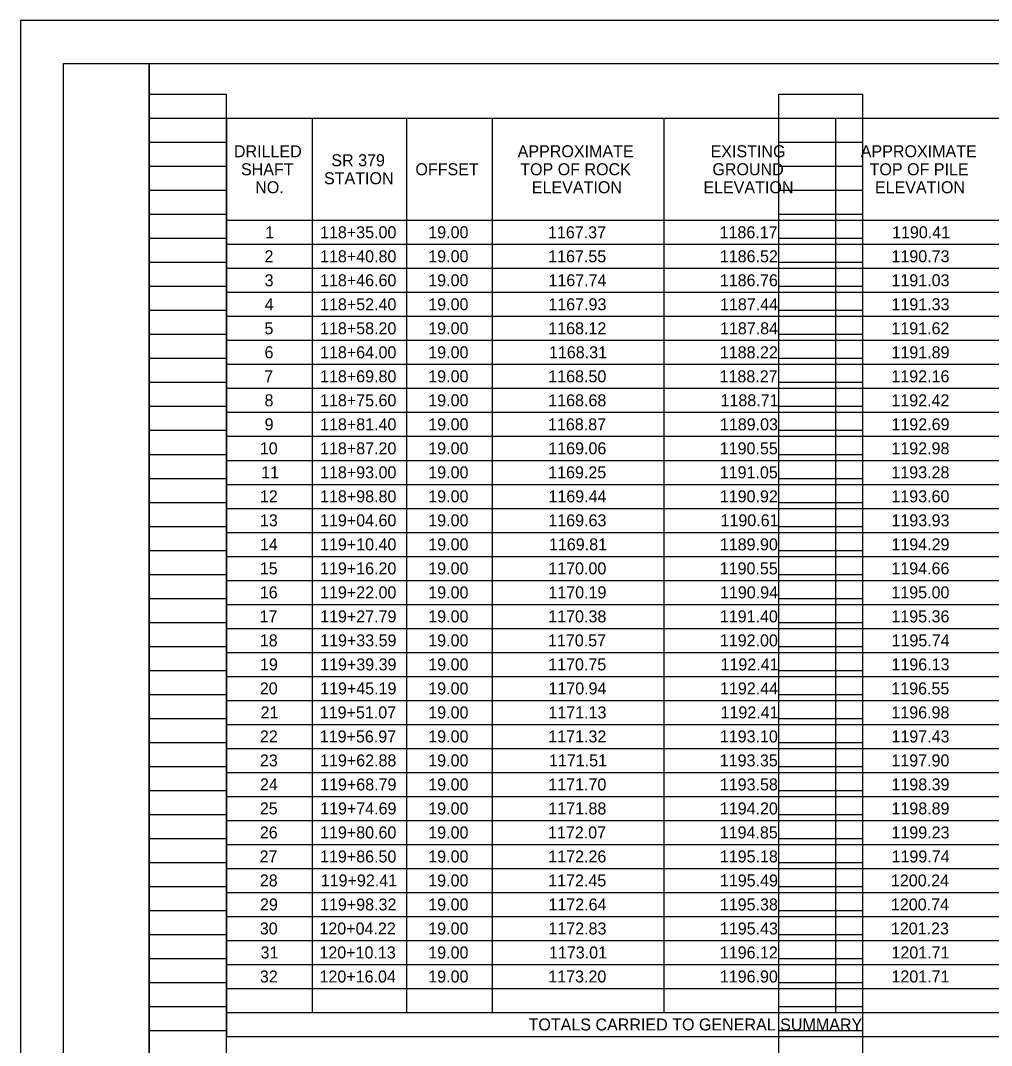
# Model space of a CAD drawing. Extents: x 0 to 34, y 0 to 22.
# Drawn here: x 0 to 11.32, y 10.04 to 22 of the extents above; entities that cross this region are included whole.
import ezdxf

# ---------------------------------------------------------------- set-up
doc = ezdxf.new("R2010")
doc.units = 0
for name, color, linetype in [('RD_P_Text', 7, 'Continuous'), ('SC_Scratch1', 7, 'Continuous'), ('SC_Scratch2', 7, 'Continuous'), ('SH_Border', 7, 'Continuous'), ('SH_Cut_Line', 7, 'Continuous')]:
    doc.layers.add(name, color=color, linetype=linetype)

msp = doc.modelspace()

# ---------------------------------------------------------------- linework, layer by layer
at = {"layer": 'RD_P_Text'}
for p, q in [((2.4, 20.86), (20.1, 20.86)), ((2.4, 20.86), (2.4, 10.15)), ((3.4, 20.86), (3.4, 10.43)), ((4.5, 20.86), (4.5, 10.43)), ((5.5, 20.86), (5.5, 10.43)), ((7.5, 20.86), (7.5, 10.43)), ((9.5, 20.86), (9.5, 10.43)), ((2.4, 19.67), (20.1, 19.67)), ((2.4, 19.39), (20.1, 19.39)), ((2.4, 19.11), (20.1, 19.11)), ((2.4, 18.83), (20.1, 18.83)), ((2.4, 18.55), (20.1, 18.55)), ((2.4, 18.27), (20.1, 18.27)), ((2.4, 17.99), (20.1, 17.99)), ((2.4, 17.71), (20.1, 17.71)), ((2.4, 17.43), (20.1, 17.43)), ((2.4, 17.15), (20.1, 17.15)), ((2.4, 16.87), (20.1, 16.87)), ((2.4, 16.59), (20.1, 16.59)), ((2.4, 16.31), (20.1, 16.31)), ((2.4, 16.03), (20.1, 16.03)), ((2.4, 15.75), (20.1, 15.75)), ((2.4, 15.47), (20.1, 15.47)), ((2.4, 15.19), (20.1, 15.19)), ((2.4, 14.91), (20.1, 14.91)), ((2.4, 14.63), (20.1, 14.63)), ((2.4, 14.35), (20.1, 14.35)), ((2.4, 14.07), (20.1, 14.07)), ((2.4, 13.79), (20.1, 13.79)), ((2.4, 13.51), (20.1, 13.51)), ((2.4, 13.23), (20.1, 13.23)), ((2.4, 12.95), (20.1, 12.95)), ((2.4, 12.67), (20.1, 12.67)), ((2.4, 12.39), (20.1, 12.39)), ((2.4, 12.11), (20.1, 12.11)), ((2.4, 11.83), (20.1, 11.83)), ((2.4, 11.55), (20.1, 11.55)), ((2.4, 11.27), (20.1, 11.27)), ((2.4, 10.99), (20.1, 10.99)), ((2.4, 10.71), (20.1, 10.71)), ((2.4, 10.43), (20.1, 10.43)), ((2.4, 10.15), (20.1, 10.15))]:
    msp.add_line(p, q, dxfattribs=at)
at = {"layer": 'SC_Scratch1'}
for p, q in [((2.9, 19.53), (2.9, 19.53)), ((3.95, 19.53), (3.95, 19.53)), ((5, 19.53), (5, 19.53)), ((6.5, 19.53), (6.5, 19.53)), ((8.5, 19.53), (8.5, 19.53)), ((10.5, 19.53), (10.5, 19.53)), ((2.9, 19.25), (2.9, 19.25)), ((3.95, 19.25), (3.95, 19.25)), ((5, 19.25), (5, 19.25)), ((6.5, 19.25), (6.5, 19.25)), ((8.5, 19.25), (8.5, 19.25)), ((10.5, 19.25), (10.5, 19.25)), ((2.9, 18.97), (2.9, 18.97)), ((3.95, 18.97), (3.95, 18.97)), ((5, 18.97), (5, 18.97)), ((6.5, 18.97), (6.5, 18.97)), ((8.5, 18.97), (8.5, 18.97)), ((10.5, 18.97), (10.5, 18.97)), ((2.9, 18.69), (2.9, 18.69)), ((3.95, 18.69), (3.95, 18.69)), ((5, 18.69), (5, 18.69)), ((6.5, 18.69), (6.5, 18.69)), ((8.5, 18.69), (8.5, 18.69)), ((10.5, 18.69), (10.5, 18.69)), ((2.9, 18.41), (2.9, 18.41)), ((3.95, 18.41), (3.95, 18.41)), ((5, 18.41), (5, 18.41)), ((6.5, 18.41), (6.5, 18.41)), ((8.5, 18.41), (8.5, 18.41)), ((10.5, 18.41), (10.5, 18.41)), ((2.9, 18.13), (2.9, 18.13)), ((3.95, 18.13), (3.95, 18.13)), ((5, 18.13), (5, 18.13)), ((6.5, 18.13), (6.5, 18.13)), ((8.5, 18.13), (8.5, 18.13)), ((10.5, 18.13), (10.5, 18.13)), ((2.9, 17.85), (2.9, 17.85)), ((3.95, 17.85), (3.95, 17.85)), ((5, 17.85), (5, 17.85)), ((6.5, 17.85), (6.5, 17.85)), ((8.5, 17.85), (8.5, 17.85)), ((10.5, 17.85), (10.5, 17.85)), ((2.9, 17.57), (2.9, 17.57)), ((3.95, 17.57), (3.95, 17.57)), ((5, 17.57), (5, 17.57)), ((6.5, 17.57), (6.5, 17.57)), ((8.5, 17.57), (8.5, 17.57)), ((10.5, 17.57), (10.5, 17.57)), ((2.9, 17.29), (2.9, 17.29)), ((3.95, 17.29), (3.95, 17.29)), ((5, 17.29), (5, 17.29)), ((6.5, 17.29), (6.5, 17.29)), ((8.5, 17.29), (8.5, 17.29)), ((10.5, 17.29), (10.5, 17.29)), ((2.9, 17.01), (2.9, 17.01)), ((3.95, 17.01), (3.95, 17.01)), ((5, 17.01), (5, 17.01)), ((6.5, 17.01), (6.5, 17.01)), ((8.5, 17.01), (8.5, 17.01)), ((10.5, 17.01), (10.5, 17.01)), ((2.9, 16.73), (2.9, 16.73)), ((3.95, 16.73), (3.95, 16.73)), ((5, 16.73), (5, 16.73)), ((6.5, 16.73), (6.5, 16.73)), ((8.5, 16.73), (8.5, 16.73)), ((10.5, 16.73), (10.5, 16.73)), ((2.9, 16.45), (2.9, 16.45)), ((3.95, 16.45), (3.95, 16.45)), ((5, 16.45), (5, 16.45)), ((6.5, 16.45), (6.5, 16.45)), ((8.5, 16.45), (8.5, 16.45)), ((10.5, 16.45), (10.5, 16.45)), ((2.9, 16.17), (2.9, 16.17)), ((3.95, 16.17), (3.95, 16.17)), ((5, 16.17), (5, 16.17)), ((6.5, 16.17), (6.5, 16.17)), ((8.5, 16.17), (8.5, 16.17)), ((10.5, 16.17), (10.5, 16.17)), ((2.9, 15.89), (2.9, 15.89)), ((3.95, 15.89), (3.95, 15.89)), ((5, 15.89), (5, 15.89)), ((6.5, 15.89), (6.5, 15.89)), ((8.5, 15.89), (8.5, 15.89)), ((10.5, 15.89), (10.5, 15.89)), ((2.9, 15.61), (2.9, 15.61)), ((3.95, 15.61), (3.95, 15.61)), ((5, 15.61), (5, 15.61)), ((6.5, 15.61), (6.5, 15.61)), ((8.5, 15.61), (8.5, 15.61)), ((10.5, 15.61), (10.5, 15.61)), ((2.9, 15.33), (2.9, 15.33)), ((3.95, 15.33), (3.95, 15.33)), ((5, 15.33), (5, 15.33)), ((6.5, 15.33), (6.5, 15.33)), ((8.5, 15.33), (8.5, 15.33)), ((10.5, 15.33), (10.5, 15.33)), ((2.9, 15.05), (2.9, 15.05)), ((3.95, 15.05), (3.95, 15.05)), ((5, 15.05), (5, 15.05)), ((6.5, 15.05), (6.5, 15.05)), ((8.5, 15.05), (8.5, 15.05)), ((10.5, 15.05), (10.5, 15.05)), ((2.9, 14.77), (2.9, 14.77)), ((3.95, 14.77), (3.95, 14.77)), ((5, 14.77), (5, 14.77)), ((6.5, 14.77), (6.5, 14.77)), ((8.5, 14.77), (8.5, 14.77)), ((10.5, 14.77), (10.5, 14.77)), ((2.9, 14.49), (2.9, 14.49)), ((3.95, 14.49), (3.95, 14.49)), ((5, 14.49), (5, 14.49)), ((6.5, 14.49), (6.5, 14.49)), ((8.5, 14.49), (8.5, 14.49)), ((10.5, 14.49), (10.5, 14.49)), ((2.9, 14.21), (2.9, 14.21)), ((3.95, 14.21), (3.95, 14.21)), ((5, 14.21), (5, 14.21)), ((6.5, 14.21), (6.5, 14.21)), ((8.5, 14.21), (8.5, 14.21)), ((10.5, 14.21), (10.5, 14.21)), ((2.9, 13.93), (2.9, 13.93)), ((3.95, 13.93), (3.95, 13.93)), ((5, 13.93), (5, 13.93)), ((6.5, 13.93), (6.5, 13.93)), ((8.5, 13.93), (8.5, 13.93)), ((10.5, 13.93), (10.5, 13.93)), ((2.9, 13.65), (2.9, 13.65)), ((3.95, 13.65), (3.95, 13.65)), ((5, 13.65), (5, 13.65)), ((6.5, 13.65), (6.5, 13.65)), ((8.5, 13.65), (8.5, 13.65)), ((10.5, 13.65), (10.5, 13.65)), ((2.9, 13.37), (2.9, 13.37)), ((3.95, 13.37), (3.95, 13.37)), ((5, 13.37), (5, 13.37)), ((6.5, 13.37), (6.5, 13.37)), ((8.5, 13.37), (8.5, 13.37)), ((10.5, 13.37), (10.5, 13.37)), ((2.9, 13.09), (2.9, 13.09)), ((3.95, 13.09), (3.95, 13.09)), ((5, 13.09), (5, 13.09)), ((6.5, 13.09), (6.5, 13.09)), ((8.5, 13.09), (8.5, 13.09)), ((10.5, 13.09), (10.5, 13.09)), ((2.9, 12.81), (2.9, 12.81)), ((3.95, 12.81), (3.95, 12.81)), ((5, 12.81), (5, 12.81)), ((6.5, 12.81), (6.5, 12.81)), ((8.5, 12.81), (8.5, 12.81)), ((10.5, 12.81), (10.5, 12.81)), ((2.9, 12.53), (2.9, 12.53)), ((3.95, 12.53), (3.95, 12.53)), ((5, 12.53), (5, 12.53)), ((6.5, 12.53), (6.5, 12.53)), ((8.5, 12.53), (8.5, 12.53)), ((10.5, 12.53), (10.5, 12.53)), ((2.9, 12.25), (2.9, 12.25)), ((3.95, 12.25), (3.95, 12.25)), ((5, 12.25), (5, 12.25)), ((6.5, 12.25), (6.5, 12.25)), ((8.5, 12.25), (8.5, 12.25)), ((10.5, 12.25), (10.5, 12.25)), ((2.9, 11.97), (2.9, 11.97)), ((3.95, 11.97), (3.95, 11.97)), ((5, 11.97), (5, 11.97)), ((6.5, 11.97), (6.5, 11.97)), ((8.5, 11.97), (8.5, 11.97)), ((10.5, 11.97), (10.5, 11.97)), ((2.9, 11.69), (2.9, 11.69)), ((3.95, 11.69), (3.95, 11.69)), ((5, 11.69), (5, 11.69)), ((6.5, 11.69), (6.5, 11.69)), ((8.5, 11.69), (8.5, 11.69)), ((10.5, 11.69), (10.5, 11.69)), ((2.9, 11.41), (2.9, 11.41)), ((3.95, 11.41), (3.95, 11.41)), ((5, 11.41), (5, 11.41)), ((6.5, 11.41), (6.5, 11.41)), ((8.5, 11.41), (8.5, 11.41)), ((10.5, 11.41), (10.5, 11.41)), ((2.9, 11.13), (2.9, 11.13)), ((3.95, 11.13), (3.95, 11.13)), ((5, 11.13), (5, 11.13)), ((6.5, 11.13), (6.5, 11.13)), ((8.5, 11.13), (8.5, 11.13)), ((10.5, 11.13), (10.5, 11.13)), ((2.9, 10.85), (2.9, 10.85)), ((3.95, 10.85), (3.95, 10.85)), ((5, 10.85), (5, 10.85)), ((6.5, 10.85), (6.5, 10.85)), ((8.5, 10.85), (8.5, 10.85)), ((10.5, 10.85), (10.5, 10.85))]:
    msp.add_line(p, q, dxfattribs=at)
at = {"layer": 'SC_Scratch2'}
for p, q in [((1.5, 0.98), (1.5, 21.14)), ((1.5, 21.14), (2.4, 21.14)), ((2.4, 0.98), (2.4, 21.14)), ((8.84, 0.98), (8.84, 21.14)), ((8.84, 21.14), (9.82, 21.14)), ((9.82, 0.98), (9.82, 21.14)), ((1.5, 20.86), (2.4, 20.86)), ((8.84, 20.86), (9.82, 20.86)), ((1.5, 20.58), (2.4, 20.58)), ((8.84, 20.58), (9.82, 20.58)), ((1.5, 20.3), (2.4, 20.3)), ((8.84, 20.3), (9.82, 20.3)), ((1.5, 20.02), (2.4, 20.02)), ((8.84, 20.02), (9.82, 20.02)), ((1.5, 19.74), (2.4, 19.74)), ((8.84, 19.74), (9.82, 19.74)), ((1.5, 19.46), (2.4, 19.46)), ((8.84, 19.46), (9.82, 19.46)), ((1.5, 19.18), (2.4, 19.18)), ((8.84, 19.18), (9.82, 19.18)), ((1.5, 18.9), (2.4, 18.9)), ((8.84, 18.9), (9.82, 18.9)), ((1.5, 18.62), (2.4, 18.62)), ((8.84, 18.62), (9.82, 18.62)), ((1.5, 18.34), (2.4, 18.34)), ((8.84, 18.34), (9.82, 18.34)), ((1.5, 18.06), (2.4, 18.06)), ((8.84, 18.06), (9.82, 18.06)), ((1.5, 17.78), (2.4, 17.78)), ((8.84, 17.78), (9.82, 17.78)), ((1.5, 17.5), (2.4, 17.5)), ((8.84, 17.5), (9.82, 17.5)), ((1.5, 17.22), (2.4, 17.22)), ((8.84, 17.22), (9.82, 17.22)), ((1.5, 16.94), (2.4, 16.94)), ((8.84, 16.94), (9.82, 16.94)), ((1.5, 16.66), (2.4, 16.66)), ((8.84, 16.66), (9.82, 16.66)), ((1.5, 16.38), (2.4, 16.38)), ((8.84, 16.38), (9.82, 16.38)), ((1.5, 16.1), (2.4, 16.1)), ((8.84, 16.1), (9.82, 16.1)), ((1.5, 15.82), (2.4, 15.82)), ((8.84, 15.82), (9.82, 15.82)), ((1.5, 15.54), (2.4, 15.54)), ((8.84, 15.54), (9.82, 15.54)), ((1.5, 15.26), (2.4, 15.26)), ((8.84, 15.26), (9.82, 15.26)), ((1.5, 14.98), (2.4, 14.98)), ((8.84, 14.98), (9.82, 14.98)), ((1.5, 14.7), (2.4, 14.7)), ((8.84, 14.7), (9.82, 14.7)), ((1.5, 14.42), (2.4, 14.42)), ((8.84, 14.42), (9.82, 14.42)), ((1.5, 14.14), (2.4, 14.14)), ((8.84, 14.14), (9.82, 14.14)), ((1.5, 13.86), (2.4, 13.86)), ((8.84, 13.86), (9.82, 13.86)), ((1.5, 13.58), (2.4, 13.58)), ((8.84, 13.58), (9.82, 13.58)), ((1.5, 13.3), (2.4, 13.3)), ((8.84, 13.3), (9.82, 13.3)), ((1.5, 13.02), (2.4, 13.02)), ((8.84, 13.02), (9.82, 13.02)), ((1.5, 12.74), (2.4, 12.74)), ((8.84, 12.74), (9.82, 12.74)), ((1.5, 12.46), (2.4, 12.46)), ((8.84, 12.46), (9.82, 12.46)), ((1.5, 12.18), (2.4, 12.18)), ((8.84, 12.18), (9.82, 12.18)), ((1.5, 11.9), (2.4, 11.9)), ((8.84, 11.9), (9.82, 11.9)), ((1.5, 11.62), (2.4, 11.62)), ((8.84, 11.62), (9.82, 11.62)), ((1.5, 11.34), (2.4, 11.34)), ((8.84, 11.34), (9.82, 11.34)), ((1.5, 11.06), (2.4, 11.06)), ((8.84, 11.06), (9.82, 11.06)), ((1.5, 10.78), (2.4, 10.78)), ((8.84, 10.78), (9.82, 10.78)), ((1.5, 10.5), (2.4, 10.5)), ((8.84, 10.5), (9.82, 10.5)), ((1.5, 10.22), (2.4, 10.22)), ((8.84, 10.22), (9.82, 10.22))]:
    msp.add_line(p, q, dxfattribs=at)
at = {"layer": 'SH_Border'}
for points in [[(0.5, 21.5), (1.5, 21.5), (1.5, 0.5), (0.5, 0.5)], [(1.5, 21.5), (33.5, 21.5), (33.5, 0.5), (1.5, 0.5)]]:
    msp.add_lwpolyline(points, close=True, dxfattribs=at)
at = {"layer": 'SH_Cut_Line'}
msp.add_lwpolyline([(0, 0), (34, 0), (34, 22), (0, 22)], close=True, dxfattribs=at)

# ---------------------------------------------------------------- texts
at = {"layer": 'RD_P_Text'}
for s, p in [('DRILLED', (2.488, 20.405)), ('APPROXIMATE', (5.796, 20.405)), ('EXISTING', (8.045, 20.405)), ('APPROXIMATE', (9.796, 20.405)), ('SHAFT', (2.57, 20.195)), ('SR 379', (3.624, 20.3)), ('OFFSET', (4.604, 20.195)), ('TOP OF ROCK', (5.826, 20.195)), ('GROUND', (8.066, 20.195)), ('TOP OF PILE', (9.899, 20.195)), ('STATION', (3.538, 20.09)), ('NO.', (2.736, 19.985)), ('ELEVATION', (5.961, 19.985)), ('ELEVATION', (7.961, 19.985)), ('ELEVATION', (9.961, 19.985)), ('1', (2.853, 19.46)), ('118+35.00', (3.492, 19.46)), ('19.00', (4.754, 19.46)), ('1167.37', (6.15, 19.46)), ('1186.17', (8.15, 19.46)), ('1190.41', (10.161, 19.46)), ('2', (2.845, 19.18)), ('118+40.80', (3.492, 19.18)), ('19.00', (4.754, 19.18)), ('1167.55', (6.152, 19.18)), ('1186.52', (8.153, 19.18)), ('1190.73', (10.154, 19.18)), ('3', (2.846, 18.9)), ('118+46.60', (3.492, 18.9)), ('19.00', (4.754, 18.9)), ('1167.74', (6.155, 18.9)), ('1186.76', (8.153, 18.9)), ('1191.03', (10.154, 18.9)), ('4', (2.847, 18.62)), ('118+52.40', (3.492, 18.62)), ('19.00', (4.754, 18.62)), ('1167.93', (6.154, 18.62)), ('1187.44', (8.155, 18.62)), ('1191.33', (10.154, 18.62)), ('5', (2.844, 18.34)), ('118+58.20', (3.492, 18.34)), ('19.00', (4.754, 18.34)), ('1168.12', (6.153, 18.34)), ('1187.84', (8.155, 18.34)), ('1191.62', (10.153, 18.34)), ('6', (2.845, 18.06)), ('118+64.00', (3.492, 18.06)), ('19.00', (4.754, 18.06)), ('1168.31', (6.161, 18.06)), ('1188.22', (8.153, 18.06)), ('1191.89', (10.154, 18.06)), ('7', (2.842, 17.78)), ('118+69.80', (3.492, 17.78)), ('19.00', (4.754, 17.78)), ('1168.50', (6.153, 17.78)), ('1188.27', (8.15, 17.78)), ('1192.16', (10.153, 17.78)), ('8', (2.845, 17.5)), ('8', (2.845, 17.5)), ('118+75.60', (3.492, 17.5)), ('19.00', (4.754, 17.5)), ('1168.68', (6.153, 17.5)), ('1188.71', (8.161, 17.5)), ('1192.42', (10.153, 17.5)), ('9', (2.846, 17.22)), ('118+81.40', (3.492, 17.22)), ('19.00', (4.754, 17.22)), ('1168.87', (6.15, 17.22)), ('1189.03', (8.154, 17.22)), ('1192.69', (10.154, 17.22)), ('10', (2.79, 16.94)), ('118+87.20', (3.492, 16.94)), ('19.00', (4.754, 16.94)), ('1169.06', (6.153, 16.94)), ('1190.55', (8.152, 16.94)), ('1192.98', (10.153, 16.94)), ('11', (2.806, 16.66)), ('118+93.00', (3.492, 16.66)), ('19.00', (4.754, 16.66)), ('1169.25', (6.152, 16.66)), ('1191.05', (8.152, 16.66)), ('1193.28', (10.153, 16.66)), ('12', (2.791, 16.38)), ('118+98.80', (3.492, 16.38)), ('19.00', (4.754, 16.38)), ('1169.44', (6.155, 16.38)), ('1190.92', (8.153, 16.38)), ('1193.60', (10.153, 16.38)), ('13', (2.791, 16.1)), ('119+04.60', (3.492, 16.1)), ('19.00', (4.754, 16.1)), ('1169.63', (6.154, 16.1)), ('1190.61', (8.161, 16.1)), ('1193.93', (10.154, 16.1)), ('14', (2.792, 15.82)), ('119+10.40', (3.492, 15.82)), ('19.00', (4.754, 15.82)), ('1169.81', (6.161, 15.82)), ('1189.90', (8.153, 15.82)), ('1194.29', (10.154, 15.82)), ('15', (2.79, 15.54)), ('119+16.20', (3.492, 15.54)), ('19.00', (4.754, 15.54)), ('1170.00', (6.153, 15.54)), ('1190.55', (8.152, 15.54)), ('1194.66', (10.153, 15.54)), ('16', (2.79, 15.26)), ('119+22.00', (3.492, 15.26)), ('19.00', (4.754, 15.26)), ('1170.19', (6.154, 15.26)), ('1190.94', (8.155, 15.26)), ('1195.00', (10.153, 15.26)), ('17', (2.787, 14.98)), ('119+27.79', (3.493, 14.98)), ('19.00', (4.754, 14.98)), ('1170.38', (6.153, 14.98)), ('1191.40', (8.153, 14.98)), ('1195.36', (10.153, 14.98)), ('18', (2.79, 14.7)), ('119+33.59', (3.493, 14.7)), ('19.00', (4.754, 14.7)), ('1170.57', (6.15, 14.7)), ('1192.00', (8.153, 14.7)), ('1195.74', (10.155, 14.7)), ('19', (2.792, 14.42)), ('119+39.39', (3.493, 14.42)), ('19.00', (4.754, 14.42)), ('1170.75', (6.152, 14.42)), ('1192.41', (8.161, 14.42)), ('1196.13', (10.154, 14.42)), ('20', (2.79, 14.14)), ('119+45.19', (3.493, 14.14)), ('19.00', (4.754, 14.14)), ('1170.94', (6.155, 14.14)), ('1192.44', (8.155, 14.14)), ('1196.55', (10.152, 14.14)), ('21', (2.799, 13.86)), ('119+51.07', (3.489, 13.86)), ('19.00', (4.754, 13.86)), ('1171.13', (6.154, 13.86)), ('1192.41', (8.161, 13.86)), ('1196.98', (10.153, 13.86)), ('22', (2.791, 13.58)), ('119+56.97', (3.489, 13.58)), ('19.00', (4.754, 13.58)), ('1171.32', (6.153, 13.58)), ('1193.10', (8.153, 13.58)), ('1197.43', (10.154, 13.58)), ('23', (2.791, 13.3)), ('119+62.88', (3.492, 13.3)), ('19.00', (4.754, 13.3)), ('1171.51', (6.161, 13.3)), ('1193.35', (8.152, 13.3)), ('1197.90', (10.153, 13.3)), ('24', (2.792, 13.02)), ('119+68.79', (3.493, 13.02)), ('19.00', (4.754, 13.02)), ('1171.70', (6.153, 13.02)), ('1193.58', (8.153, 13.02)), ('1198.39', (10.154, 13.02)), ('25', (2.79, 12.74)), ('119+74.69', (3.493, 12.74)), ('19.00', (4.754, 12.74)), ('1171.88', (6.153, 12.74)), ('1194.20', (8.153, 12.74)), ('1198.89', (10.154, 12.74)), ('26', (2.79, 12.46)), ('119+80.60', (3.492, 12.46)), ('19.00', (4.754, 12.46)), ('1172.07', (6.15, 12.46)), ('1194.85', (8.152, 12.46)), ('1199.23', (10.154, 12.46)), ('27', (2.787, 12.18)), ('119+86.50', (3.492, 12.18)), ('19.00', (4.754, 12.18)), ('1172.26', (6.153, 12.18)), ('1195.18', (8.153, 12.18)), ('1199.74', (10.155, 12.18)), ('28', (2.79, 11.9)), ('119+92.41', (3.5, 11.9)), ('19.00', (4.754, 11.9)), ('1172.45', (6.152, 11.9)), ('1195.49', (8.154, 11.9)), ('1200.24', (10.148, 11.9)), ('29', (2.792, 11.62)), ('119+98.32', (3.492, 11.62)), ('19.00', (4.754, 11.62)), ('1172.64', (6.155, 11.62)), ('1195.38', (8.153, 11.62)), ('1200.74', (10.148, 11.62)), ('30', (2.79, 11.34)), ('120+04.22', (3.485, 11.34)), ('19.00', (4.754, 11.34)), ('1172.83', (6.154, 11.34)), ('1195.43', (8.154, 11.34)), ('1201.23', (10.147, 11.34)), ('31', (2.799, 11.06)), ('120+10.13', (3.485, 11.06)), ('19.00', (4.754, 11.06)), ('1173.01', (6.161, 11.06)), ('1196.12', (8.153, 11.06)), ('1201.71', (10.154, 11.06)), ('32', (2.791, 10.78)), ('120+16.04', (3.486, 10.78)), ('19.00', (4.754, 10.78)), ('1173.20', (6.153, 10.78)), ('1196.90', (8.153, 10.78)), ('1201.71', (10.154, 10.78)), ('TOTALS CARRIED TO GENERAL SUMMARY', (5.923, 10.22))]:
    msp.add_text(s, height=0.14, dxfattribs=at).set_placement(p)

doc.saveas('drawing.dxf')
